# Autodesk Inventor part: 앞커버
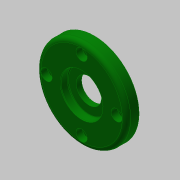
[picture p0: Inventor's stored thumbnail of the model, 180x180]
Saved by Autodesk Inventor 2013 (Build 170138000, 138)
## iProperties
Created: 2019-01
Part Number: 앞커버
Material: 일반
Document SubType Name: Modeling
Designer: mduedu
Density: 1 g/cm^3
Author: mduedu
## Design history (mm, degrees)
sketch "스케치1"
  geometry: L1 (0, 0)-(9, 0); L2 (9, 0)-(9, 32); L3 (9, 32)-(0, 32); L4 (0, 32)-(0, 0); L5 (9, 0)-(12, 0); L6 (12, 0)-(12, 20); L7 (12, 20)-(9, 20); L8 (9, 20)-(9, 0)
  constraints: 16 end point, 4 parallel, 2 horizontal, 2 perpendicular
  dimensions: "d0" = 12 distance between parallel lines of L6 L4; "d2" = 64 diameter of L3 L1; "d3" = 40 diameter of L7 L5; "d4" = 3 distance between parallel lines of L6 L2
revolve "회전1" sketch "스케치1" stored, may be unused: angle "d5" = 90 deg
sketch "스케치2"
  geometry: L1 (0, -32)-(0, 32) reference; L2 (0, 32)-(9, 32) reference; L3 (9, 32)-(9, 20) reference; L4 (9, 20)-(12, 20) reference; L5 (12, 20)-(12, -20) reference; L6 (12, -20)-(9, -20) reference; L7 (9, -20)-(9, -32) reference; L8 (9, -32)-(0, -32) reference; L9 (0, 0)-(5.2, 0); L10 (5.2, 0)-(5.2, 15); L11 (5.2, 15)-(0, 15); L12 (0, 15)-(0, 0); L13 (5.2, 0)-(9, 0); L14 (9, 0)-(9, 9); L15 (9, 9)-(5.2, 9); L16 (5.2, 9)-(5.2, 0); L17 (9, 0)-(12, 0); L18 (12, 0)-(12, 15); L19 (12, 15)-(9, 15); L20 (9, 15)-(9, 0)
  constraints: 24 end point, 6 parallel, 3 horizontal, 3 perpendicular, 1 point on line
  dimensions: "d6" = 3 distance of L18.end L19.end; "d8" = 5.2 distance of L10.end L11.end; "d9" = 30 diameter of L11 L9; "d10" = 18 diameter of L15 L13; "d11" = 30 diameter of L19 L17
revolve "회전2" sketch "스케치2" stored, may be unused: angle "d12" = 90 deg
chamfer "모따기1" distance "d13" = 0.5; stored, may be unused: second distance "d14" = 2, angle "d15" = 30 deg
fillet "모깎기1" dims "d16" = 0.5
fillet "모깎기2" dims "d17" = 3
fillet "모깎기3" dims "d18" = 3
chamfer "모따기2" distance "d24" = 1; stored, may be unused: second distance "d25" = 2, angle "d26" = 45 deg
sketch "스케치3" dims "d19" = 50
  geometry: 6 further points
  constraints: 2 vertical alignment, 1 coincident, 7 other
  dimensions: "d22" = 360 deg dimension on point (0, 0) point (0, 25) (derived)
sketch "스케치4"
  geometry: 4 further points
  constraints: 4 other
hole "구멍1" sketch "스케치4" at (-25, 0), (0, -25), (25, 0), (0, 25) diameter "d27" = 4.5; stored, may be unused: countersink angle "d31" = 90 deg, drill point angle "d33" = 0 deg; dims "d28" = 6, "d29" = 8, "d30" = 4.6, "d32" = 8
node "솔리드1"
node "절단 모서리 투영1"
